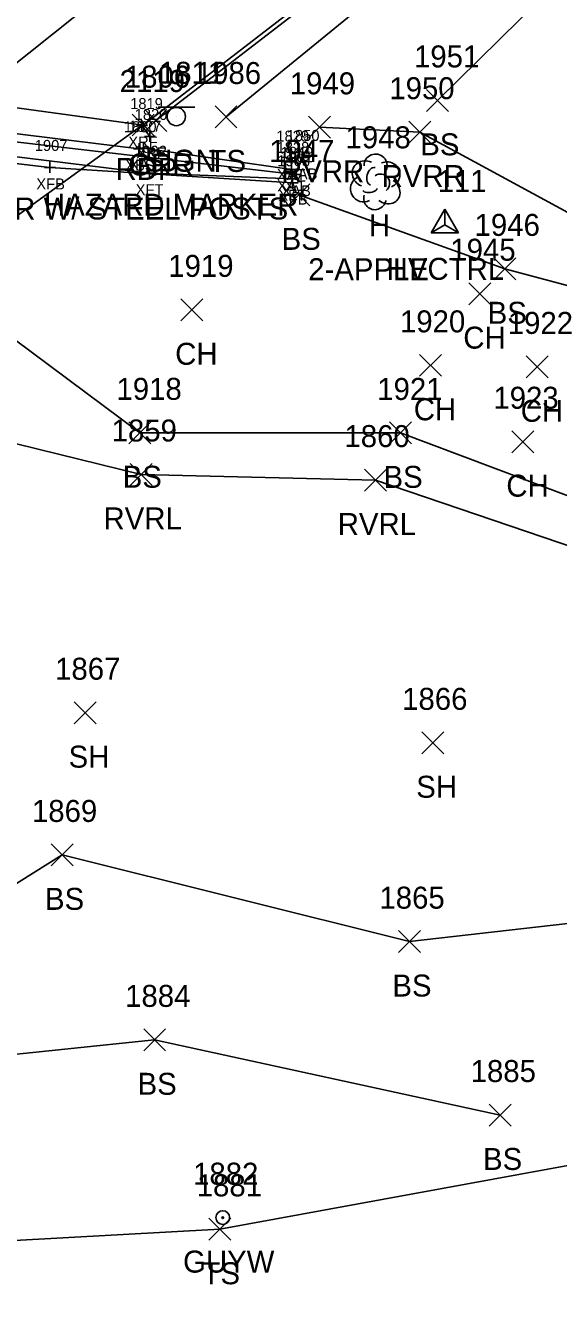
# Model space of a CAD drawing. Extents: x 1633660 to 1636532, y 388643 to 392631.
# Drawn here: x 1634493.7 to 1634542.2, y 388865.4 to 388982.1 of the extents above; entities that cross this region are included whole.
import ezdxf

# ---------------------------------------------------------------- set-up
doc = ezdxf.new("R2010")
doc.units = 0
for name, color, linetype in [('B_A', 7, 'Continuous'), ('B_I', 7, 'Continuous'), ('B_TIC', 7, 'Continuous'), ('BFT', 7, 'Continuous'), ('BR', 7, 'Continuous'), ('BSE', 7, 'Continuous'), ('BSUBM', 7, 'Continuous'), ('C_A', 7, 'Continuous'), ('C_I', 7, 'Continuous'), ('CPSM', 7, 'Continuous'), ('L_A', 7, 'Continuous'), ('L_C', 7, 'Continuous'), ('L_I', 7, 'Continuous'), ('L_TIC', 7, 'Continuous'), ('LAWE', 7, 'Continuous'), ('LELB', 7, 'Continuous'), ('LTD', 7, 'Continuous'), ('P_A', 7, 'Continuous'), ('P_I', 7, 'Continuous'), ('P_TIC', 7, 'Continuous'), ('PET', 7, 'Continuous'), ('PRC', 7, 'Continuous'), ('R_A', 7, 'Continuous'), ('R_C', 7, 'Continuous'), ('R_I', 7, 'Continuous'), ('R_TIC', 7, 'Continuous'), ('RGR', 7, 'Continuous'), ('S_A', 7, 'Continuous'), ('S_C', 7, 'Continuous'), ('S_I', 7, 'Continuous'), ('SSGN', 7, 'Continuous'), ('U_A', 7, 'Continuous'), ('U_I', 7, 'Continuous'), ('UPGW', 7, 'Continuous')]:
    doc.layers.add(name, color=color, linetype=linetype)

msp = doc.modelspace()

# ---------------------------------------------------------------- linework, layer by layer
at = {"layer": 'B_TIC'}
for p, q in [((1634504.26, 388972.99), (1634504.34, 388972.99)), ((1634504.99, 388972), (1634505.07, 388972)), ((1634504.01, 388970.88), (1634504.08, 388970.88)), ((1634504.4, 388970.92), (1634504.48, 388970.92)), ((1634495.89, 388969.18), (1634495.96, 388969.18)), ((1634517.86, 388970.03), (1634517.94, 388970.03)), ((1634518.85, 388970.09), (1634518.93, 388970.09)), ((1634504.95, 388968.65), (1634505.02, 388968.65)), ((1634517.88, 388968.99), (1634517.96, 388968.99)), ((1634517.95, 388968.15), (1634518.03, 388968.15)), ((1634518.25, 388968.55), (1634518.33, 388968.55)), ((1634517.99, 388967.79), (1634518.07, 388967.79))]:
    msp.add_line(p, q, dxfattribs=at)
for points in [[(1634503.76, 388972.99), (1634504.76, 388972.99)], [(1634504.26, 388972.49), (1634504.26, 388973.49)], [(1634504.49, 388972), (1634505.49, 388972)], [(1634504.99, 388971.5), (1634504.99, 388972.5)], [(1634503.5, 388970.88), (1634504.5, 388970.88)], [(1634503.9, 388970.92), (1634504.9, 388970.92)], [(1634504, 388970.38), (1634504, 388971.38)], [(1634504.4, 388970.42), (1634504.4, 388971.42)], [(1634517.86, 388969.53), (1634517.86, 388970.53)], [(1634518.85, 388969.59), (1634518.85, 388970.59)], [(1634495.38, 388969.18), (1634496.38, 388969.18)], [(1634495.88, 388968.68), (1634495.88, 388969.68)], [(1634504.94, 388968.15), (1634504.94, 388969.15)], [(1634517.36, 388970.03), (1634518.36, 388970.03)], [(1634517.88, 388968.49), (1634517.88, 388969.49)], [(1634518.35, 388970.09), (1634519.35, 388970.09)], [(1634504.44, 388968.65), (1634505.44, 388968.65)], [(1634517.38, 388968.99), (1634518.38, 388968.99)], [(1634517.45, 388968.15), (1634518.45, 388968.15)], [(1634517.75, 388968.55), (1634518.75, 388968.55)], [(1634517.95, 388967.65), (1634517.95, 388968.65)], [(1634517.99, 388967.29), (1634517.99, 388968.29)], [(1634518.25, 388968.05), (1634518.25, 388969.05)], [(1634517.49, 388967.79), (1634518.49, 388967.79)]]:
    msp.add_lwpolyline(points, dxfattribs=at)
at = {"layer": 'BFT'}
for points in [[(1634517.95, 388968.15), (1634504.94, 388968.65), (1634461.71, 388973.98), (1634461.66, 388975.01)], [(1634461.48, 388973.95), (1634476.15, 388971.47), (1634495.88, 388969.18), (1634517.99, 388967.79)]]:
    msp.add_lwpolyline(points, dxfattribs=at)
at = {"layer": 'BR'}
msp.add_lwpolyline([(1634481.47, 388955.1), (1634480.89, 388956.14), (1634504.26, 388972.99), (1634504.99, 388972)], dxfattribs=at)
at = {"layer": 'BSE'}
msp.add_lwpolyline([(1634504, 388970.88), (1634469.21, 388975.15)], dxfattribs=at)
at = {"layer": 'BSUBM'}
for points in [[(1634461.23, 388981.53), (1634461.93, 388975.08), (1634518.25, 388968.55), (1634518.85, 388970.09)], [(1634504.4, 388970.92), (1634517.88, 388968.99), (1634517.86, 388970.03)]]:
    msp.add_lwpolyline(points, dxfattribs=at)
at = {"layer": 'CPSM'}
for p, q in [((1634530.61, 388963.23), (1634531.86, 388965.39)), ((1634533.11, 388963.23), (1634531.86, 388965.39)), ((1634531.86, 388963.95), (1634531.86, 388965.39)), ((1634530.61, 388963.23), (1634531.86, 388963.95)), ((1634531.86, 388963.95), (1634531.86, 388963.95)), ((1634531.86, 388963.95), (1634533.11, 388963.23)), ((1634530.61, 388963.23), (1634533.11, 388963.23))]:
    msp.add_line(p, q, dxfattribs=at)
at = {"layer": 'L_TIC'}
for points in [[(1634530.18, 388974.28), (1634532.18, 388976.28)], [(1634532.18, 388974.28), (1634530.18, 388976.28)], [(1634510.92, 388972.77), (1634512.92, 388974.77)], [(1634512.92, 388972.77), (1634510.92, 388974.77)], [(1634519.43, 388971.83), (1634521.43, 388973.83)], [(1634521.43, 388971.83), (1634519.43, 388973.83)], [(1634528.58, 388971.39), (1634530.58, 388973.39)], [(1634530.58, 388971.39), (1634528.58, 388973.39)], [(1634517.55, 388965.68), (1634519.55, 388967.68)], [(1634519.55, 388965.68), (1634517.55, 388967.68)], [(1634536.32, 388958.95), (1634538.32, 388960.95)], [(1634538.32, 388958.95), (1634536.32, 388960.95)], [(1634534.05, 388956.69), (1634536.05, 388958.69)], [(1634536.05, 388956.69), (1634534.05, 388958.69)], [(1634507.8, 388955.22), (1634509.8, 388957.22)], [(1634509.8, 388955.22), (1634507.8, 388957.22)], [(1634529.55, 388950.17), (1634531.55, 388952.17)], [(1634531.55, 388950.17), (1634529.55, 388952.17)], [(1634539.28, 388950.03), (1634541.28, 388952.03)], [(1634541.28, 388950.03), (1634539.28, 388952.03)], [(1634503.06, 388944.03), (1634505.06, 388946.03)], [(1634505.06, 388944.03), (1634503.06, 388946.03)], [(1634526.82, 388944.02), (1634528.82, 388946.02)], [(1634528.82, 388944.02), (1634526.82, 388946.02)], [(1634537.97, 388943.22), (1634539.97, 388945.22)], [(1634539.97, 388943.22), (1634537.97, 388945.22)], [(1634503.2, 388940.24), (1634505.2, 388942.24)], [(1634505.2, 388940.24), (1634503.2, 388942.24)], [(1634524.53, 388939.73), (1634526.53, 388941.73)], [(1634526.53, 388939.73), (1634524.53, 388941.73)], [(1634498.09, 388918.56), (1634500.09, 388920.56)], [(1634500.09, 388918.56), (1634498.09, 388920.56)], [(1634529.77, 388915.82), (1634531.77, 388917.82)], [(1634531.77, 388915.82), (1634529.77, 388917.82)], [(1634495.98, 388905.62), (1634497.98, 388907.62)], [(1634497.98, 388905.62), (1634495.98, 388907.62)], [(1634527.64, 388897.73), (1634529.64, 388899.73)], [(1634529.64, 388897.73), (1634527.64, 388899.73)], [(1634504.42, 388888.79), (1634506.42, 388890.79)], [(1634506.42, 388888.79), (1634504.42, 388890.79)], [(1634535.9, 388881.95), (1634537.9, 388883.95)], [(1634537.9, 388881.95), (1634535.9, 388883.95)], [(1634510.37, 388871.55), (1634512.37, 388873.55)], [(1634512.37, 388871.55), (1634510.37, 388873.55)]]:
    msp.add_lwpolyline(points, dxfattribs=at)
at = {"layer": 'LAWE'}
for points in [[(1634485.27, 388945.87), (1634504.2, 388941.24), (1634525.53, 388940.73), (1634548.51, 388932.94), (1634584.66, 388920), (1634598.75, 388914.41), (1634618.8, 388928.88), (1634638.3, 388944.91), (1634660.99, 388957.08), (1634677.58, 388983.24), (1634696.95, 389006.4), (1634707.36, 389033.31), (1634727.93, 389056.72), (1634749.89, 389078.7), (1634762.92, 389095.06), (1634797.9, 389102.54), (1634816.33, 389112.04), (1634824.18, 389130.77), (1634824.18, 389150.65), (1634818.45, 389174.95), (1634815.05, 389205.92), (1634802.11, 389220.82), (1634788.76, 389226.82)], [(1634520.43, 388972.83), (1634529.58, 388972.39), (1634557.27, 388957.37), (1634580.07, 388955.67), (1634596.48, 388954.83), (1634611.77, 388964.29), (1634628.48, 388986.24), (1634647.88, 389006.91), (1634658.84, 389024.3), (1634672.7, 389044.33), (1634690.56, 389064.6), (1634720.63, 389097.89), (1634743.8, 389121.88), (1634765.96, 389139.81), (1634789.88, 389159.93), (1634790.78, 389168.23), (1634779.52, 389189.43), (1634780.72, 389197.89), (1634770.08, 389207.77)]]:
    msp.add_lwpolyline(points, dxfattribs=at)
at = {"layer": 'LELB'}
for points in [[(1634531.18, 388975.28), (1634550.04, 388993.84), (1634582.85, 389016.58), (1634590.99, 389033.59), (1634624.25, 389062.77), (1634653.38, 389090.44), (1634686.4, 389120.7), (1634717.26, 389150.25), (1634744.21, 389175.48), (1634771.92, 389200.56)], [(1634703.21, 389149.54), (1634682.53, 389132.47), (1634655.74, 389104.45), (1634622.93, 389072.78), (1634589.92, 389040.08), (1634578.99, 389022.4), (1634560.52, 389008.32), (1634535.52, 388993.05), (1634511.92, 388973.77)], [(1634617.86, 388956.31), (1634597.1, 388947.99), (1634578.19, 388950.92), (1634563.38, 388953.01), (1634537.32, 388959.95), (1634518.55, 388966.68)], [(1634486.03, 388958.42), (1634504.06, 388945.03), (1634527.82, 388945.02), (1634547.83, 388937.52), (1634559.74, 388934.65), (1634574.19, 388927.83), (1634589.05, 388923.96), (1634604.77, 388924.76), (1634617.83, 388931.52), (1634629.87, 388942.08)], [(1634584.89, 388915.4), (1634565.24, 388902.91), (1634528.64, 388898.73), (1634496.98, 388906.62), (1634477.85, 388894.65), (1634446.93, 388893.09), (1634415.16, 388876.74), (1634407.22, 388862.91), (1634384.25, 388848.4), (1634365.18, 388835.86)], [(1634366.11, 388829.23), (1634392.92, 388840.96), (1634414.75, 388860.24), (1634439.48, 388873.42), (1634473.36, 388870.48), (1634511.37, 388872.55), (1634556.17, 388880.75), (1634584.64, 388898.02), (1634601.64, 388909.04)], [(1634480.86, 388887.23), (1634505.42, 388889.79), (1634536.9, 388882.95)]]:
    msp.add_lwpolyline(points, dxfattribs=at)
at = {"layer": 'LTD'}
msp.add_line((1634525.5, 388967.92), (1634525.5, 388967.92), dxfattribs=at)
msp.add_line((1634525.5, 388967.92), (1634525.5, 388967.92), dxfattribs=at)
msp.add_arc((1634525.55, 388969.35), 1.05, 335.5272, 180.9563, dxfattribs=at)
for centre, major_axis, ratio, start_param, end_param in [((1634524.71, 388968.58), (1.21, -0.51), 0.895232, 1.570796, 4.712389), ((1634525.29, 388968.37), (-0.208, -0.792), 0.645439, 3.141593, 6.283185), ((1634526.54, 388968.5), (-1.14, -0.48), 0.949671, 1.570796, 4.712389), ((1634524.42, 388967.21), (0.58, -1.04), 0.959034, 3.141593, 6.283185), ((1634526, 388967.75), (-0.5, 0.667), 0.989748, 3.141593, 6.283185), ((1634526.5, 388967.08), (-1.09, 0.79), 0.841452, 1.570796, 4.712389), ((1634525.04, 388967.17), (-0.625, -0.083), 0.423636, 0, 3.141593), ((1634525.5, 388966.42), (0.26, 1.06), 0.942809, 1.570796, 4.712389)]:
    msp.add_ellipse(centre, major_axis=major_axis, ratio=ratio, start_param=start_param, end_param=end_param, dxfattribs=at)
at = {"layer": 'P_TIC'}
for points in [[(1634503.36, 388972.04), (1634505.36, 388974.04)], [(1634505.36, 388972.04), (1634503.36, 388974.04)]]:
    msp.add_lwpolyline(points, dxfattribs=at)
at = {"layer": 'PET'}
msp.add_lwpolyline([(1634682.08, 389181.1), (1634650.7, 389146.38), (1634620.25, 389115.23), (1634604.63, 389098.3), (1634579.1, 389070.12), (1634546.56, 389039.3), (1634509.68, 389006.46), (1634474.11, 388976.77), (1634488.61, 388975.18), (1634504.36, 388973.04), (1634532.03, 388994.36), (1634563.21, 389020.04), (1634596.33, 389051.02), (1634641.93, 389096.55), (1634679.61, 389135.06), (1634705.94, 389161.6), (1634722.45, 389175.59), (1634749.3, 389203.85), (1634763.45, 389218.45), (1634753.18, 389229.52), (1634742.76, 389239.64), (1634704.36, 389200.19), (1634691.63, 389189.01)], dxfattribs=at)
at = {"layer": 'PRC'}
msp.add_lwpolyline([(1634489.59, 388976.11), (1634524.5, 389003.94), (1634553.65, 389029.27), (1634589.65, 389062.97), (1634628.75, 389101.27), (1634671.28, 389144.58), (1634699.51, 389173.36), (1634712.64, 389186.75), (1634739.32, 389214.16), (1634752.84, 389228.98)], dxfattribs=at)
at = {"layer": 'R_TIC'}
for points in [[(1634504.53, 388972.44), (1634506.53, 388974.44)], [(1634506.53, 388972.44), (1634504.53, 388974.44)]]:
    msp.add_lwpolyline(points, dxfattribs=at)
at = {"layer": 'RGR'}
msp.add_lwpolyline([(1634505.53, 388973.44), (1634535.84, 388996.77), (1634558.43, 389013.91), (1634571.07, 389021.77), (1634577.72, 389024.58)], dxfattribs=at)
at = {"layer": 'SSGN'}
for p, q in [((1634505.75, 388974.65), (1634509.08, 388974.65)), ((1634507.39, 388973.81), (1634507.39, 388973.81))]:
    msp.add_line(p, q, dxfattribs=at)
msp.add_circle((1634507.39, 388973.81), 0.833, dxfattribs=at)
at = {"layer": 'UPGW'}
for radius in [0.625, 0.0833]:
    msp.add_circle((1634511.62, 388873.61), radius, dxfattribs=at)

# ---------------------------------------------------------------- texts
at = {"layer": 'B_A'}
for s, p in [('XRF', (1634503.02, 388970.99)), ('XRF', (1634503.75, 388970)), ('XBS', (1634502.74, 388968.88)), ('XAT', (1634503.1, 388968.92)), ('XFB', (1634494.64, 388967.18)), ('XAT', (1634516.56, 388968.03)), ('XAT', (1634516.58, 388966.99)), ('XAB', (1634517.57, 388968.09)), ('XFT', (1634503.69, 388966.65)), ('XFT', (1634516.69, 388966.15)), ('XAB', (1634516.97, 388966.55)), ('XFB', (1634516.75, 388965.79))]:
    msp.add_text(s, height=1, dxfattribs=at).set_placement(p)
at = {"layer": 'B_I'}
for s, p in [('1819', (1634503.19, 388974.49)), ('1820', (1634503.6, 388973.5)), ('1830', (1634502.61, 388972.38)), ('1827', (1634503.05, 388972.42)), ('1907', (1634494.5, 388970.68)), ('1829', (1634516.51, 388971.53)), ('1828', (1634516.53, 388970.49)), ('1850', (1634517.46, 388971.59)), ('1902', (1634503.56, 388970.15)), ('1901', (1634516.85, 388969.65)), ('1849', (1634516.9, 388970.05)), ('1908', (1634516.6, 388969.29))]:
    msp.add_text(s, height=1, dxfattribs=at).set_placement(p)
at = {"layer": 'C_A'}
msp.add_text('HVCTRL', height=2, dxfattribs=at).set_placement((1634526.56, 388958.95))
at = {"layer": 'C_I'}
msp.add_text('111', height=2, dxfattribs=at).set_placement((1634531.2, 388966.95))
at = {"layer": 'L_A'}
for s, p in [('BS', (1634529.62, 388970.28)), ('TS', (1634510.33, 388968.77)), ('RVRR', (1634516.94, 388967.83)), ('RVRR', (1634526.1, 388967.39)), ('H', (1634524.93, 388962.92)), ('BS', (1634516.99, 388961.68)), ('BS', (1634535.76, 388954.95)), ('CH', (1634533.54, 388952.69)), ('CH', (1634507.29, 388951.22)), ('CH', (1634529.03, 388946.17)), ('CH', (1634538.77, 388946.03)), ('BS', (1634502.51, 388940.03)), ('BS', (1634526.27, 388940.02)), ('CH', (1634537.46, 388939.22)), ('RVRL', (1634500.76, 388936.24)), ('RVRL', (1634522.1, 388935.73)), ('SH', (1634497.58, 388914.56)), ('SH', (1634529.25, 388911.82)), ('BS', (1634495.43, 388901.62)), ('BS', (1634527.08, 388893.73)), ('BS', (1634503.86, 388884.79)), ('BS', (1634535.34, 388877.95)), ('TS', (1634509.78, 388867.55))]:
    msp.add_text(s, height=2, dxfattribs=at).set_placement(p)
at = {"layer": 'L_C'}
msp.add_text('2-APPLE', height=2, dxfattribs=at).set_placement((1634519.41, 388958.92))
at = {"layer": 'L_I'}
for s, p in [('1951', (1634529.05, 388978.28)), ('1986', (1634509.17, 388976.77)), ('1949', (1634517.73, 388975.83)), ('1950', (1634526.8, 388975.39)), ('1948', (1634522.81, 388970.92)), ('1947', (1634515.85, 388969.68)), ('1946', (1634534.57, 388962.95)), ('1945', (1634532.36, 388960.69)), ('1919', (1634506.66, 388959.22)), ('1920', (1634527.77, 388954.17)), ('1922', (1634537.59, 388954.03)), ('1918', (1634501.94, 388948.03)), ('1921', (1634525.7, 388948.02)), ('1923', (1634536.28, 388947.22)), ('1859', (1634501.5, 388944.24)), ('1860', (1634522.71, 388943.73)), ('1867', (1634496.35, 388922.56)), ('1866', (1634527.97, 388919.82)), ('1869', (1634494.24, 388909.62)), ('1865', (1634525.9, 388901.73)), ('1884', (1634502.73, 388892.79)), ('1885', (1634534.21, 388885.95)), ('1881', (1634509.25, 388875.55))]:
    msp.add_text(s, height=2, dxfattribs=at).set_placement(p)
at = {"layer": 'P_A'}
msp.add_text('RDP', height=2, dxfattribs=at).set_placement((1634501.85, 388968.04))
at = {"layer": 'P_I'}
msp.add_text('2119', height=2, dxfattribs=at).set_placement((1634502.23, 388976.04))
at = {"layer": 'R_A'}
msp.add_text('GRR', height=2, dxfattribs=at).set_placement((1634503.02, 388968.44))
at = {"layer": 'R_C'}
msp.add_text('SGR W/ STEEL POSTS', height=2, dxfattribs=at).set_placement((1634488.76, 388964.44))
at = {"layer": 'R_I'}
msp.add_text('1806', height=2, dxfattribs=at).set_placement((1634502.7, 388976.44))
at = {"layer": 'S_A'}
msp.add_text('SIGN', height=2, dxfattribs=at).set_placement((1634504.53, 388968.79))
at = {"layer": 'S_C'}
msp.add_text('HAZARD MARKER', height=2, dxfattribs=at).set_placement((1634495.33, 388964.79))
at = {"layer": 'S_I'}
msp.add_text('1811', height=2, dxfattribs=at).set_placement((1634505.81, 388976.79))
at = {"layer": 'U_A'}
msp.add_text('GUYW', height=2, dxfattribs=at).set_placement((1634508.01, 388868.61))
at = {"layer": 'U_I'}
msp.add_text('1882', height=2, dxfattribs=at).set_placement((1634508.92, 388876.61))

doc.saveas('drawing.dxf')
